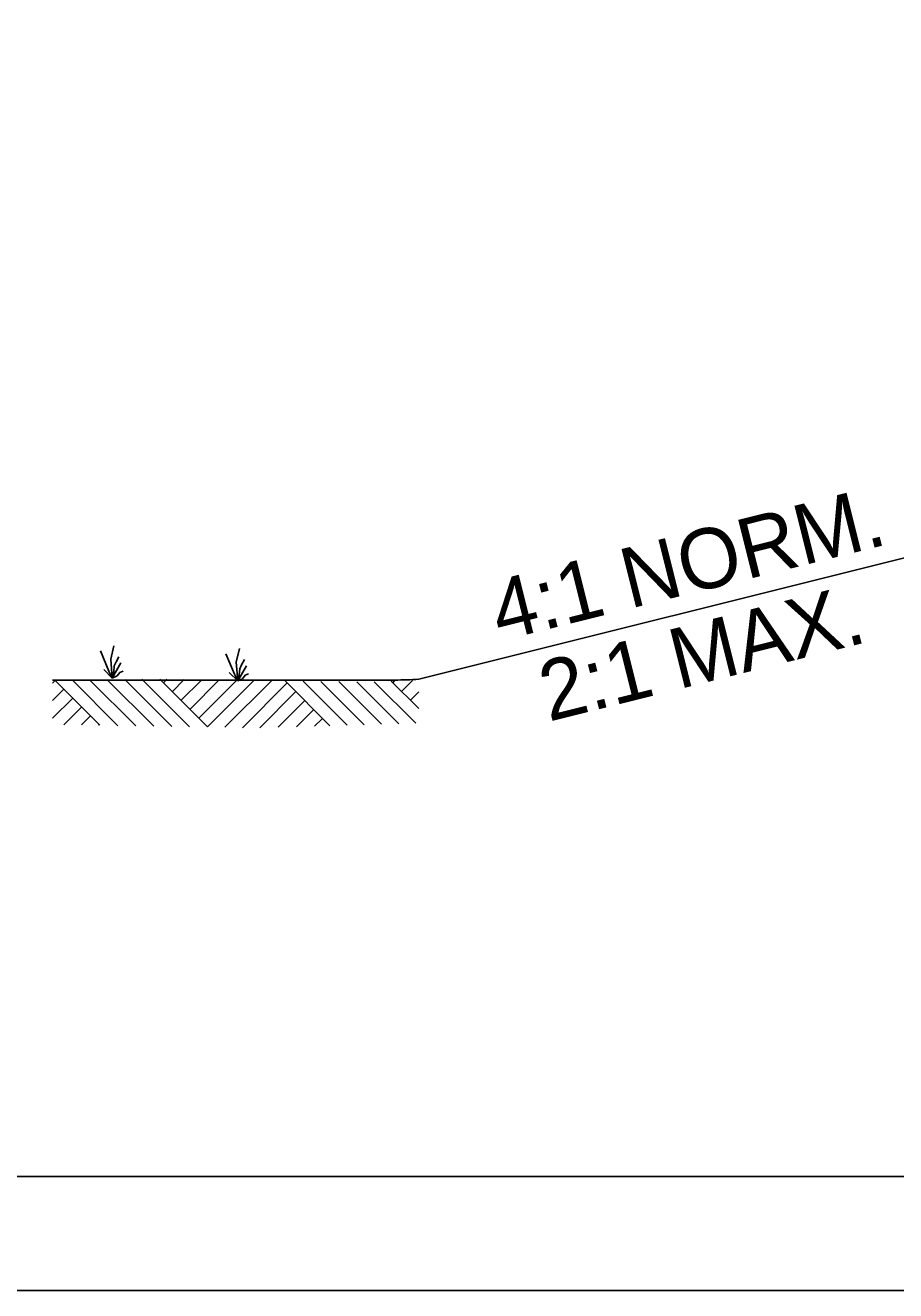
# Model space of a CAD drawing. Extents: x 1671357 to 13005564, y 567358 to 14261451.
# Drawn here: x 12758426.76 to 12758435.46, y 14259893.59 to 14259906.24 of the extents above; entities that cross this region are included whole.
import ezdxf

# ---------------------------------------------------------------- set-up
doc = ezdxf.new("R2010")
doc.units = 0
for name, color, linetype in [('Default', 7, 'Continuous'), ('R_Draft', 7, 'Continuous'), ('R_No Plot', 7, 'Continuous')]:
    doc.layers.add(name, color=color, linetype=linetype)

msp = doc.modelspace()

# ---------------------------------------------------------------- linework, layer by layer
at = {"layer": 'Default'}
for p, q in [((12758430.693, 14259899.701), (12758441.603, 14259902.429)), ((12758427.593, 14259899.782), (12758427.508, 14259899.987)), ((12758427.611, 14259899.902), (12758427.643, 14259900.037)), ((12758428.866, 14259899.872), (12758428.898, 14259900.01)), ((12758427.626, 14259899.712), (12758427.611, 14259899.902)), ((12758427.626, 14259899.712), (12758427.713, 14259899.867)), ((12758427.646, 14259899.835), (12758427.666, 14259899.877)), ((12758427.666, 14259899.877), (12758427.693, 14259899.927)), ((12758428.848, 14259899.752), (12758428.763, 14259899.957)), ((12758428.881, 14259899.685), (12758428.866, 14259899.872)), ((12758428.921, 14259899.847), (12758428.948, 14259899.9)), ((12758427.626, 14259899.712), (12758427.541, 14259899.8)), ((12758427.626, 14259899.712), (12758427.593, 14259899.782)), ((12758427.626, 14259899.712), (12758427.641, 14259899.775)), ((12758427.626, 14259899.712), (12758427.676, 14259899.735)), ((12758427.641, 14259899.775), (12758427.646, 14259899.835)), ((12758427.676, 14259899.735), (12758427.701, 14259899.77)), ((12758427.701, 14259899.77), (12758427.736, 14259899.782)), ((12758428.881, 14259899.685), (12758428.796, 14259899.77)), ((12758428.881, 14259899.685), (12758428.848, 14259899.752)), ((12758428.881, 14259899.685), (12758428.968, 14259899.837)), ((12758428.881, 14259899.685), (12758428.896, 14259899.745)), ((12758428.896, 14259899.745), (12758428.901, 14259899.805)), ((12758428.901, 14259899.805), (12758428.921, 14259899.847)), ((12758428.931, 14259899.707), (12758428.956, 14259899.742)), ((12758428.956, 14259899.742), (12758428.991, 14259899.755)), ((12758427.056, 14259899.69), (12758427.029, 14259899.663)), ((12758427.501, 14259899.242), (12758427.051, 14259899.692)), ((12758427.681, 14259899.237), (12758427.226, 14259899.695)), ((12758427.861, 14259899.235), (12758427.398, 14259899.697)), ((12758428.041, 14259899.232), (12758427.576, 14259899.697)), ((12758428.221, 14259899.23), (12758427.751, 14259899.7)), ((12758428.398, 14259899.227), (12758427.923, 14259899.702)), ((12758428.578, 14259899.225), (12758428.101, 14259899.702)), ((12758428.173, 14259899.702), (12758428.138, 14259899.665)), ((12758428.346, 14259899.7), (12758428.226, 14259899.577)), ((12758428.521, 14259899.697), (12758428.313, 14259899.49)), ((12758428.696, 14259899.695), (12758428.403, 14259899.4)), ((12758428.871, 14259899.692), (12758428.491, 14259899.312)), ((12758429.043, 14259899.69), (12758428.578, 14259899.225)), ((12758429.218, 14259899.687), (12758428.751, 14259899.222)), ((12758428.881, 14259899.685), (12758428.931, 14259899.707)), ((12758429.376, 14259899.665), (12758428.928, 14259899.217)), ((12758429.803, 14259899.237), (12758429.356, 14259899.685)), ((12758429.976, 14259899.242), (12758429.536, 14259899.682)), ((12758430.148, 14259899.247), (12758429.713, 14259899.68)), ((12758430.321, 14259899.252), (12758429.893, 14259899.68)), ((12758430.493, 14259899.257), (12758430.073, 14259899.677)), ((12758430.663, 14259899.262), (12758430.248, 14259899.677)), ((12758430.693, 14259899.41), (12758430.418, 14259899.682)), ((12758430.448, 14259899.685), (12758430.433, 14259899.667)), ((12758430.631, 14259899.69), (12758430.521, 14259899.58)), ((12758427.143, 14259899.602), (12758427.029, 14259899.488)), ((12758427.231, 14259899.512), (12758427.029, 14259899.311)), ((12758429.461, 14259899.575), (12758429.103, 14259899.217)), ((12758429.551, 14259899.487), (12758429.286, 14259899.222)), ((12758430.693, 14259899.575), (12758430.611, 14259899.492)), ((12758427.318, 14259899.422), (12758427.141, 14259899.245)), ((12758429.638, 14259899.397), (12758429.468, 14259899.227)), ((12758427.406, 14259899.332), (12758427.318, 14259899.245)), ((12758427.493, 14259899.245), (12758427.488, 14259899.242)), ((12758429.726, 14259899.307), (12758429.651, 14259899.232)), ((12758498.813, 14259894.727), (12758419.761, 14259894.727)), ((12758416.928, 14259893.587), (12758499.936, 14259893.587))]:
    msp.add_line(p, q, dxfattribs=at)
msp.add_spline([(12758430.693, 14259899.701), (12758430.455, 14259899.693), (12758429.943, 14259899.693), (12758429.258, 14259899.693), (12758428.758, 14259899.693), (12758427.903, 14259899.693), (12758427.075, 14259899.693), (12758427.029, 14259899.693)], degree=3, dxfattribs=at)
at = {"layer": 'R_No Plot'}
msp.add_lwpolyline([(12758416.928, 14259946.667), (12758499.936, 14259946.667), (12758499.936, 14259893.587), (12758416.928, 14259893.587)], close=True, dxfattribs=at)

# ---------------------------------------------------------------- texts
at = {"layer": 'R_Draft'}
for s, p in [('4:1 NORM.', (12758431.504, 14259900.081)), ('2:1 MAX. ', (12758431.992, 14259899.276))]:
    msp.add_text(s, height=0.6001, rotation=14.04, dxfattribs=at).set_placement(p)

doc.saveas('drawing.dxf')
